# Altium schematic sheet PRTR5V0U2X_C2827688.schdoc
size 127 x 101 mm
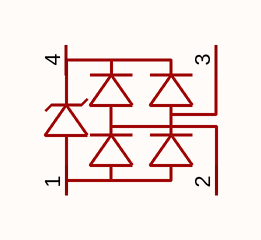
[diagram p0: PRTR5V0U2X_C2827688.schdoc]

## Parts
D?  prtr5v0u2x  [SOT-143-4_L2.9-W1.3-P1.92-LS2.4-BL]  (value not drawn)

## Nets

Not connected (* = marked no-connect by the designer): D? 1 2 3 4

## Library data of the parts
D? = prtr5v0u2x: 极性:单向;反向截止电压(Vrwm):5V;钳位电压:10V；15V;峰值脉冲电流(Ipp):6A;峰值脉冲功率(Ppp):100W;击穿电压(VBR):6.5V;; Manufacturer: TECH PUBLIC(台舟); Symbol: PRTR5V0U2X_C2827688; AddInBom: yes; ModelId: 2837e3608ba24a5fbaabe401bacde791; ModelTransform: 114.173,93.3069,0,0,0,0,-0.003,0,0; Polarity: 单向; Reverse Stand-Off Voltage (Vrwm): 5V; Peak Pulse Current (Ipp): 6A; Peak Pulse Power Dissipation (Ppp): 100W; Voltage - Breakdown: 6.5V; Reverse Leakage Current (Ir): 80nA; Number of Channels: 三路; level of protection: IEC 61000-4-2；IEC 61000-4-4；IEC 61000-4-5; Type: ESD; Junction Capacitance: 0.8pF；0.3pF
